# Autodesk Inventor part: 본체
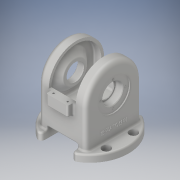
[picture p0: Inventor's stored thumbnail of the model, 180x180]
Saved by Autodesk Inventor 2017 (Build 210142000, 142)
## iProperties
Part Number: 본체
Material: 알루미늄 6061
Document SubType Name: Modeling
Designer: MRC
Density: 2.7 g/cm^3
Appearance: 알루미늄 - 평지
Mass: 1199.23 g
Surface Area: 1052.12 cm^2
Volume: 444.159 cm^3
Author: MRC
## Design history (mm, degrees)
sketch "스케치3"
  geometry: C1 r 71 at (0, 0); 1 further point
  constraints: 1 centre point, 1 coincident
  dimensions: "d4" = 142 diameter of C1
extrude "돌출2" new body sketch "스케치3" distance "d5" = 13; taper "d6" = 0 deg
sketch "스케치4"
  geometry: L1 (-44, -51)-(44, -51); L2 (44, -51)-(44, 51); L3 (44, 51)-(-44, 51); L4 (-44, 51)-(-44, -51); L5 (-44, -51)-(44, 51); L6 (44, -51)-(-44, 51); 1 further point
  constraints: 12 end point, 2 midpoint, 2 parallel, 1 horizontal, 1 perpendicular
  dimensions: "d7" = 88 distance of L3.end L2.end; "d8" = 102 distance of L2.end L1.end
extrude "돌출3" join sketch "스케치4" distance "d9" = 119; taper "d10" = 0 deg
fillet "모깎기1" dims "d11" = 51
node "작업 평면1"
sketch "스케치6"
  geometry: L1 (28, -19)-(-28, -19); L2 (-28, -19)-(-28, 19); L3 (-28, 19)-(28, 19); L4 (28, 19)-(28, -19); L5 (28, -19)-(-28, 19); L6 (-28, -19)-(28, 19); 1 further point
  constraints: 12 end point, 2 midpoint, 2 parallel, 1 horizontal, 1 perpendicular
  dimensions: "d13" = 56 distance of L2.end L3.end; "d14" = 38 distance of L1.end L2.end
extrude "돌출4" cut sketch "스케치6" stored distance "d15" = 81; taper "d16" = 0 deg
node "작업 평면3"
sketch "스케치9"
  geometry: L1 (20, -61)-(-20, -61); L2 (-20, -61)-(-20, 61); L3 (-20, 61)-(20, 61); L4 (20, 61)-(20, -61); L5 (20, -61)-(-20, 61); L6 (-20, -61)-(20, 61); 1 further point
  constraints: 12 end point, 2 midpoint, 2 parallel, 1 horizontal, 1 perpendicular
  dimensions: "d18" = 122 distance of L3.end L1.start; "d19" = 40 distance of L2.end L3.end
extrude "돌출5" join sketch "스케치9" distance "d20" = 20; taper "d21" = 0 deg
sketch "스케치11"
  geometry: L1 (13, 51)-(81, 51) reference; L2 (13, -51)-(81, -51) reference; L3 (40, 46)-(81, 46); L4 (81, -46)-(40, -46); L5 (40, 46)-(40, -46); L6 (0, -65.246)-(0, 65.246) reference; A1 r 51 centre (81, 0) between (81, -51) and (81, 51) reference; A2 r 46 centre (81, 0) between (81, -46) and (81, 46); 1 further point
  constraints: 6 end point, 2 point on circle, 1 centre point
  dimensions: "d22" = 5 radial gap between concentric circles of A1 A2; "d23" = 40 distance between parallel lines of L5 L6; "d24" = 5 distance between parallel lines of L2 L4; "d25" = 5 distance between parallel lines of L1 L3
extrude "돌출6" cut sketch "스케치11" stored distance "d26" = 78; taper "d27" = 0 deg
sketch "스케치12"
  geometry: L1 (-25, 183)-(25, 183); L2 (25, 183)-(25, 81); L3 (25, 81)-(-25, 81); L4 (-25, 81)-(-25, 183); L5 (-44, 132)-(44, 132) reference; L6 (-25, 183)-(25, 81); L7 (25, 183)-(-25, 81); 2 further points
  constraints: 12 end point, 3 midpoint, 2 parallel, 1 horizontal, 1 perpendicular
  dimensions: "d28" = 50 distance of L1.start L1.end; "d29" = 102 distance of L1.end L2.end
extrude "돌출7" cut sketch "스케치12" stored distance "d30" = 150; taper "d31" = 0 deg
sketch "스케치13"
  geometry: L1 (25, 81)-(-25, 81) reference; L2 (39, 81)-(25, 81) reference; L3 (-25, 81)-(-39, 81) reference; L4 (-39, 127)-(-39, 81) reference; L5 (-39, 114.5)-(-27, 102.5); L6 (-27, 102.5)-(-27, 81); L7 (-39, 81)-(-39, 114.5); L8 (-39, 127)-(-25, 127) reference; L9 (-39, 81)-(-27, 81); 1 further point
  constraints: 8 end point, 2 point on line, 1 collinear, 1 parallel, 1 vertical
  dimensions: "d32" = 12 horizontal distance of L5.start L5.end; "d33" = 45 deg angle of L5 L8; "d34" = 67 diameter of L5.start L3
revolve "회전1" sketch "스케치13" stored, may be unused: angle "d35" = 90 deg
sketch "스케치15"
  geometry: C1 r 30 at (51, 68); A1 r 51 centre (51, 68) between (102, 68) and (0, 68) reference; 1 further point
  constraints: 1 centre point, 1 coincident
  dimensions: "d36" = 60 diameter of C1
extrude "돌출8" cut sketch "스케치15" distance "d37" = 2; taper "d38" = 0 deg
sketch "스케치16"
  geometry: C1 r 30 at (0, 0) reference; C2 r 18.5 at (0, 0); 1 further point
  constraints: 1 centre point, 1 coincident
  dimensions: "d39" = 37 diameter of C2
extrude "돌출9" cut sketch "스케치16" distance "d40" = 13; taper "d41" = 0 deg
sketch "스케치17"
  geometry: C1 r 18.5 at (0, 0) reference; C2 r 16 at (0, 0); 1 further point
  constraints: 1 centre point, 1 coincident
  dimensions: "d42" = 32 diameter of C2
extrude "돌출10" cut sketch "스케치17" distance "d43" = 13; taper "d44" = 0 deg
sketch "스케치18"
  geometry: C1 r 16 at (0, 0) reference; A1 r 23 centre (0, 0) between (0, 23) and (23, 0); 3 further points
  constraints: 4 point on circle, 2 horizontal alignment, 2 vertical alignment, 1 centre point, 1 coincident
  dimensions: "d45" = 46 diameter of A1
hole "구멍1" sketch "스케치18" at (0, 23), (23, 0), (0, -23), (-23, 0) diameter "d46" = 3.242; stored, may be unused: countersink angle "d50" = 90 deg, drill point angle "d52" = 118 deg; dims "d47" = 8, "d48" = 4, "d49" = 2, "d51" = 10
sketch "스케치20"
  geometry: C1 r 30 at (0, 0); 1 further point
  constraints: 1 centre point, 1 coincident
  dimensions: "d56" = 60 diameter of C1
extrude "돌출12" cut sketch "스케치20" distance "d57" = 22; taper "d58" = 0 deg
sketch "스케치21"
  geometry: C1 r 14 at (0, 0); 1 further point
  constraints: 1 centre point, 1 coincident
  dimensions: "d59" = 28 diameter of C1
extrude "돌출13" cut sketch "스케치21" distance "d60" = 15; taper "d61" = 0 deg
sketch "스케치22"
  geometry: C1 r 11 at (0, 0); 1 further point
  constraints: 1 centre point, 1 coincident
  dimensions: "d62" = 22 diameter of C1
extrude "돌출14" cut sketch "스케치22" stored distance "d63" = 15; taper "d64" = 0 deg
sketch "스케치23"
  geometry: A1 r 23 centre (0, 0) between (0, -23) and (-23, 0); 3 further points
  constraints: 4 point on circle, 2 horizontal alignment, 2 vertical alignment, 1 centre point, 1 coincident
  dimensions: "d65" = 46 diameter of A1
hole "구멍2" sketch "스케치23" at (0, -23), (-23, 0), (0, 23), (23, 0) diameter "d66" = 3.242; stored, may be unused: countersink angle "d70" = 90 deg, drill point angle "d72" = 118 deg; dims "d67" = 8, "d68" = 4, "d69" = 2, "d71" = 10
sketch "스케치24"
  geometry: L1 (-55, -25)-(55, -25); L2 (55, -25)-(55, 25); L3 (55, 25)-(-55, 25); L4 (-55, 25)-(-55, -25); L5 (-55, -25)-(55, 25); L6 (55, -25)-(-55, 25); A1 r 30 centre (0, 0) between (28, -10.77) and (28, 10.77) reference; A2 r 30 centre (0, 0) between (-28, 10.77) and (-28, -10.77) reference; 5 further points
  constraints: 12 end point, 4 coincident, 2 midpoint, 2 parallel, 1 horizontal, 1 perpendicular
  dimensions: "d73" = 110 distance of L3.end L2.end; "d74" = 50 distance of L2.end L1.end
hole "구멍3" sketch "스케치24" at (55, 25), (55, -25), (-55, 25), (-55, -25) diameter "d75" = 9; stored, may be unused: countersink angle "d79" = 90 deg, drill point angle "d81" = 118 deg; dims "d76" = 8, "d77" = 15, "d78" = 8.8, "d80" = 22
sketch "스케치25"
  geometry: L1 (-13, 54)-(13, 54); L2 (13, 54)-(13, -54); L3 (13, -54)-(-13, -54); L4 (-13, -54)-(-13, 54); L5 (-13, 54)-(13, -54); L6 (13, 54)-(-13, -54); 5 further points
  constraints: 12 end point, 4 coincident, 2 midpoint, 2 parallel, 1 horizontal, 1 perpendicular
  dimensions: "d82" = 26 distance of L2.end L3.end; "d83" = 108 distance of L1.end L2.end
hole "구멍4" sketch "스케치25" at (13, 54), (-13, 54), (-13, -54), (13, -54) diameter "d84" = 3.242; stored, may be unused: countersink angle "d88" = 90 deg, drill point angle "d90" = 118 deg; dims "d85" = 8, "d86" = 15, "d87" = 8.8, "d89" = 10
sketch "스케치26"
  geometry: L1 (-14.246, -13)-(116.246, -13) reference; 3 further points
  constraints: 1 midpoint, 1 vertical alignment, 1 other
  dimensions: "d91" = 30 distance from line of point (51, 17) L1
feature "엠보싱1" sketch "스케치26" dims "d13" = 56, "d14" = 38, "d92" = 0.5, "d93" = 0
fillet "모깎기2" dims "d94" = 8
fillet "모깎기3" dims "d95" = 6
chamfer "모따기1" distance "d96" = 1; stored, may be unused: second distance "d97" = 2, angle "d98" = 45 deg
fillet "모깎기4" dims "d99" = 3
fillet "모깎기5" dims "d100" = 3
fillet "모깎기6" dims "d101" = 0.3
node "솔리드2"
mirror "미러1"
other parameters: "d12" = 71, "d17" = 81
